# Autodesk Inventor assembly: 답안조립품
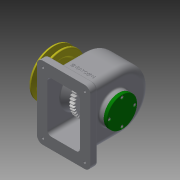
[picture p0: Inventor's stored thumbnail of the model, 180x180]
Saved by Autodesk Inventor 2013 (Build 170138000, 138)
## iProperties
Created: 2016-10
Part Number: 답안조립품
Document SubType Name: Assembly
Designer: Administrator
Author: Administrator
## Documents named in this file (15)
- C:\Users\Administrator\Desktop\461007v1003\답안조립품.iam
- C:\Users\Administrator\Desktop\461007v1003\본체.ipt
- C:\Users\Administrator\Desktop\461007v1003\V-벨트풀리.ipt
- C:\Users\Administrator\Desktop\461007v1003\뒤커버.ipt
- C:\Users\Administrator\Desktop\461007v1003\멈춤나사 - M4x10.ipt
- C:\Users\Administrator\Desktop\461007v1003\베어링 6203.ipt
- C:\Users\Administrator\Desktop\461007v1003\볼트 M3 x 8.ipt
- C:\Users\Administrator\Desktop\461007v1003\볼트 M3 x 10.ipt
- C:\Users\Administrator\Desktop\461007v1003\부시.ipt
- C:\Users\Administrator\Desktop\461007v1003\스퍼기어.ipt
- C:\Users\Administrator\Desktop\461007v1003\앞커버.ipt
- C:\Users\Administrator\Desktop\461007v1003\오일씰 28 40 8.ipt
- C:\Users\Administrator\Desktop\461007v1003\축.ipt
- C:\Users\Administrator\Desktop\461007v1003\키 - 5 x 5 x 18.ipt
- C:\Users\Administrator\Desktop\461007v1003\키 - 6 x 6 x 22.ipt
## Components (9 placed, 3 different names)
1. V-벨트풀리:1
2. ISO 4762 M3 x 10:1
3. ISO 4762 M3 x 10:2
4. ISO 4762 M3 x 10:3
5. ISO 4762 M3 x 10:4
6. ISO 4762 M3 x 8:1
7. ISO 4762 M3 x 8:2
8. ISO 4762 M3 x 8:3
9. ISO 4762 M3 x 8:4
